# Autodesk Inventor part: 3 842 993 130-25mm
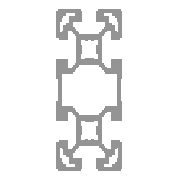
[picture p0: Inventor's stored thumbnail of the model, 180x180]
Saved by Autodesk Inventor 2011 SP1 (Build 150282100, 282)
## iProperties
Category: End -/-
Created: 2011-02
Part Number: 3 842 993 130-25mm
Document SubType Name: Modeling
Designer: SRW
Density: 2.71 g/cm^3
Categories: <MemberInstance><Categories><Category DisplayName="Structural Shapes" InternalName="089c4875-fa83-4c05-b084-43b9cc11f5ed" Mnemonic="GRDR"><CategoryParameter Dis
Stock Number: 3 842 993 130
Description: PROFILE 40x80, -/-
Material: Aluminum-6061
Mass: 65.5268 g
Surface Area: 228.528 cm^2
Volume: 24.1796 cm^3
G_L: 25.000 mm
Author: SRW
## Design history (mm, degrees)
node "Blocks"
  sketch "40X80"
    geometry: L1 (26.765, 27.076)-(27.682, 26.676); L2 (37.765, 22.28)-(36.849, 22.68); L3 (27.682, 22.68)-(26.765, 22.28); L4 (26.765, 19.178)-(29.868, 19.178); L5 (26.765, 22.28)-(26.765, 19.178); L6 (29.868, 19.178)-(30.267, 20.095); L7 (34.264, 20.095)-(34.663, 19.178); L8 (34.663, 19.178)-(37.765, 19.178); L9 (37.765, 19.178)-(37.765, 22.28); L10 (36.849, 26.676)-(37.765, 27.076); L11 (43.73, 14.628)-(39.765, 18.592); L12 (46.265, 14.628)-(43.73, 14.628); L13 (46.265, 19.678)-(46.265, 14.628); L14 (50.765, 19.678)-(46.265, 19.678); L15 (50.765, 18.878)-(50.765, 19.678); L16 (52.265, 18.878)-(50.765, 18.878); L17 (52.265, 7.787)-(52.265, 18.878); L18 (38.065, 4.787)-(49.265, 4.787); L19 (38.065, 6.287)-(38.065, 4.787); L20 (37.265, 6.287)-(38.065, 6.287); L21 (37.265, 10.787)-(37.265, 6.287); L22 (42.315, 10.787)-(37.265, 10.787); L23 (42.315, 13.322)-(42.315, 10.787); L24 (38.351, 17.287)-(42.315, 13.322); L25 (47.765, 15.178)-(47.765, 12.928); L26 (47.765, 12.928)-(46.765, 12.928); L27 (44.015, 9.178)-(41.765, 9.178); L28 (44.015, 10.178)-(44.015, 9.178); L29 (41.765, 6.178)-(46.765, 6.178); L30 (46.765, 6.178)-(46.765, 7.428); L31 (49.515, 10.178)-(50.765, 10.178); L32 (50.765, 10.178)-(50.765, 15.178); L33 (12.265, 18.878)-(12.265, 7.787); L34 (13.765, 18.878)-(12.265, 18.878); L35 (13.765, 19.678)-(13.765, 18.878); L36 (18.265, 19.678)-(13.765, 19.678); L37 (18.265, 14.628)-(18.265, 19.678); L38 (20.801, 14.628)-(18.265, 14.628); L39 (24.765, 18.592)-(20.801, 14.628); L40 (22.215, 13.322)-(26.18, 17.287); L41 (22.215, 10.787)-(22.215, 13.322); L42 (27.265, 10.787)-(22.215, 10.787); L43 (27.265, 6.287)-(27.265, 10.787); L44 (26.465, 6.287)-(27.265, 6.287); L45 (26.465, 4.787)-(26.465, 6.287); L46 (15.265, 4.787)-(26.465, 4.787); L47 (20.515, 9.178)-(20.515, 10.178); L48 (22.765, 9.178)-(20.515, 9.178); L49 (16.765, 12.928)-(16.765, 15.178); L50 (17.765, 12.928)-(16.765, 12.928); L51 (13.765, 15.178)-(13.765, 10.178); L52 (13.765, 10.178)-(15.015, 10.178); L53 (17.765, 6.178)-(22.765, 6.178); L54 (17.765, 7.428)-(17.765, 6.178); L55 (46.765, 82.145)-(46.765, 83.395); L56 (20.801, 74.945)-(24.765, 70.981); L57 (18.265, 74.945)-(20.801, 74.945); L58 (18.265, 69.895)-(18.265, 74.945); L59 (13.765, 69.895)-(18.265, 69.895); L60 (13.765, 70.695)-(13.765, 69.895); L61 (12.265, 70.695)-(13.765, 70.695); L62 (12.265, 81.787)-(12.265, 70.695); L63 (26.465, 84.787)-(15.265, 84.787); L64 (26.465, 83.287)-(26.465, 84.787)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; A1 r 5 centre (32.265, 24.678) between (36.849, 22.68) and (36.849, 26.676); A2 r 5 centre (32.265, 24.678) between (27.682, 26.676) and (27.682, 22.68); A3 r 5 centre (32.265, 24.678) between (30.267, 20.095) and (34.264, 20.095); A4 r 3 centre (49.265, 7.787) between (49.265, 4.787) and (52.265, 7.787); A5 r 1.5 centre (49.265, 15.178) between (50.765, 15.178) and (47.765, 15.178); A6 r 1.5 centre (41.765, 7.678) between (41.765, 9.178) and (41.765, 6.178); A7 r 2.75 centre (46.765, 10.178) between (46.765, 12.928) and (44.015, 10.178); A8 r 2.75 centre (46.765, 10.178) between (46.765, 7.428) and (49.515, 10.178); A9 r 3 centre (15.265, 7.787) between (12.265, 7.787) and (15.265, 4.787); A10 r 1.5 centre (15.265, 15.178) between (16.765, 15.178) and (13.765, 15.178); A11 r 2.75 centre (17.765, 10.178) between (20.515, 10.178) and (17.765, 12.928); A12 r 2.75 centre (17.765, 10.178) between (15.015, 10.178) and (17.765, 7.428); A13 r 1.5 centre (22.765, 7.678) between (22.765, 6.178) and (22.765, 9.178); A14 r 3 centre (15.265, 81.787) between (15.265, 84.787) and (12.265, 81.787); A15 r 1.5 centre (22.765, 81.895) between (22.765, 80.395) and (22.765, 83.395); A16 r 2.75 centre (17.765, 79.395) between (17.765, 76.645) and (20.515, 79.395); A17 r 1.5 centre (15.265, 74.395) between (13.765, 74.395) and (16.765, 74.395); A18 r 2.75 centre (17.765, 79.395) between (17.765, 82.145) and (15.015, 79.395); A19 r 1.5 centre (41.765, 81.895) between (41.765, 83.395) and (41.765, 80.395); A20 r 2.75 centre (46.765, 79.395) between (49.515, 79.395) and (46.765, 82.145); A21 r 2.75 centre (46.765, 79.395) between (44.015, 79.395) and (46.765, 76.645); A22 r 1.5 centre (49.265, 74.395) between (47.765, 74.395) and (50.765, 74.395); A23 r 3 centre (49.265, 81.787) between (52.265, 81.787) and (49.265, 84.787); A24 r 5 centre (32.265, 64.895) between (34.264, 69.478) and (30.267, 69.478); A25 r 5 centre (32.265, 64.895) between (36.849, 62.897) and (36.849, 66.893); A26 r 5 centre (32.265, 64.895) between (30.267, 60.312) and (34.264, 60.312); A27 r 5 centre (32.265, 64.895) between (27.682, 66.893) and (27.682, 62.897); A28 r 5 centre (32.265, 24.678) between (34.264, 29.261) and (30.267, 29.261); 1 further point
    constraints: 344 end point, 56 point on circle, 28 centre point, 1 coincident
node "Start Plane"
node "End Plane"
sketch "Sketch1"
  geometry: 1 further point
  constraints: 1 other
extrude "Body" new body sketch "Sketch1" stored distance "d4" = 0.13; taper "d5" = 0 deg
node "Driven Length"
  sketch "Sketch51"
    geometry: L1 (0, 0)-(10, 0) reference
    constraints: 2 end point, 1 horizontal
  workplane "Work Plane22"
  sketch "Sketch52"
    geometry: L1 (-28, 0)-(28, 0) reference; L2 (-28, 25)-(28, 25) reference
    dimensions: "d7" = 25 distance between parallel lines of L1 L2 (derived)
sketch "Sketch9"
  geometry: 2 further points
  constraints: 1 vertical alignment
  dimensions: "d88" = 40 distance of point (0, 0) point (0, -40)
hole "M12/-" sketch "Sketch9" at (0, 0), (0, -40) diameter "d17" = 10.106; stored, may be unused: countersink angle "d21" = 90 deg, drill point angle "d23" = 118 deg; dims "d18" = 6, "d19" = 4, "d20" = 2, "d22" = 55
sketch "Sketch10"
  geometry: 2 further points
  constraints: 1 vertical alignment
  dimensions: "d89" = 40 distance of point (0, 0) point (0, -40)
hole "-/M12" sketch "Sketch10" at (0, 0), (0, -40) diameter "d24" = 10.106; stored, may be unused: countersink angle "d28" = 90 deg, drill point angle "d30" = 118 deg; dims "d25" = 6, "d26" = 4, "d27" = 2, "d29" = 55
sketch "Sketch11"
  geometry: L1 (-13.7, 0)-(12.2, 0) reference; C1 r 8.5 at (0, 20); 1 further point
  constraints: 1 centre point, 1 vertical alignment
  dimensions: "d31" = 20 distance from line of C1.centre L1; "d32" = 17 diameter of C1
extrude "D17VS/-" cut sketch "Sketch11" stored distance "d33" = 10; taper "d34" = 0 deg
sketch "Sketch12"
  geometry: L1 (-13.7, 25)-(12.2, 25) reference; C1 r 8.5 at (0, 5); 1 further point
  constraints: 1 centre point, 1 vertical alignment
  dimensions: "d35" = 17 diameter of C1; "d36" = 20 distance from line of L1 C1.centre
extrude "-/D17VS" cut sketch "Sketch12" stored distance "d37" = 10; taper "d38" = 0 deg
sketch "Sketch13"
  geometry: L1 (-12.98, 0)-(7.88, 0) reference; C1 r 4.9 at (0, 20); 1 further point
  constraints: 1 centre point, 1 vertical alignment
  dimensions: "d39" = 9.8 diameter of C1; "d40" = 20 distance from line of C1.centre L1
extrude "D9.8VS/-" cut sketch "Sketch13" stored distance "d41" = 10; taper "d42" = 0 deg
sketch "Sketch14"
  geometry: L1 (-12.98, 25)-(7.88, 25) reference; C1 r 4.9 at (0, 5); 1 further point
  constraints: 1 centre point, 1 vertical alignment
  dimensions: "d43" = 9.8 diameter of C1; "d44" = 20 distance from line of L1 C1.centre
extrude "-/D9.8VS" cut sketch "Sketch14" stored distance "d45" = 10; taper "d46" = 0 deg
sketch "Sketch15"
  geometry: L1 (-54.86, 25)-(14.86, 25) reference; C1 r 4.9 at (0, 5); C2 r 4.9 at (-40, 5); 1 further point
  constraints: 2 centre point, 1 equal radius, 1 horizontal alignment, 1 vertical alignment
  dimensions: "d47" = 9.8 diameter of C1; "d48" = 20 distance from line of L1 C1.centre; "d92" = 40 distance of C1.centre C2.centre
extrude "-/D9.8" cut sketch "Sketch15" stored distance "d49" = 10; taper "d50" = 0 deg
sketch "Sketch26"
  geometry: L1 (-54.86, 0)-(14.86, 0) reference; C1 r 4.9 at (0, 20); C2 r 4.9 at (-40, 20); 1 further point
  constraints: 2 centre point, 1 equal radius, 1 horizontal alignment, 1 vertical alignment
  dimensions: "d62" = 9.8 diameter of C1; "d65" = 20 distance from line of L1 C1.centre; "d93" = 40 distance of C1.centre C2.centre
extrude "D9.8/-" cut sketch "Sketch26" stored distance "d63" = 10; taper "d64" = 0 deg
sketch "Sketch37"
  geometry: L1 (-59.9, 0)-(19.9, 0) reference; L2 (-59.9, 25)-(19.9, 25) reference; C1 r 8.5 at (0, 20); C2 r 8.5 at (-40, 20); 1 further point
  constraints: 2 centre point, 1 equal radius, 1 horizontal alignment, 1 vertical alignment
  dimensions: "d76" = 20 distance from line of C1.centre L1; "d77" = 17 diameter of C1; "d90" = 40 distance of C1.centre C2.centre
extrude "D17/-" cut sketch "Sketch37" stored distance "d78" = 10; taper "d79" = 0 deg
sketch "Sketch38"
  geometry: L1 (-59.9, 25)-(19.9, 25) reference; C1 r 8.5 at (0, 5); C2 r 8.5 at (-40, 5); 1 further point
  constraints: 2 centre point, 1 equal radius, 1 horizontal alignment, 1 vertical alignment
  dimensions: "d80" = 17 diameter of C1; "d81" = 20 distance from line of L1 C1.centre; "d91" = 40 distance of C1.centre C2.centre
extrude "-/D17" cut sketch "Sketch38" stored distance "d82" = 10; taper "d83" = 0 deg
body "Solid1"
node "40X80:1"
other parameters: "Length" = 25, "G_OFFSET_START" = 0 [user parameter; used in 2 equation terms], "G_OFFSET_END" = 0 [user parameter; used in 2 equation terms], "d2" = 0 (computed from G_OFFSET_START), "d3" = 25 (= Length + G_OFFSET_END), "G_L" = 25 (= d7) [user parameter], "Length2" = 25 (= G_OFFSET_START + Length + G_OFFSET_END) [user parameter], "d102" = 90 deg
